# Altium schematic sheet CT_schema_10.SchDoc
size 385 x 278 mm
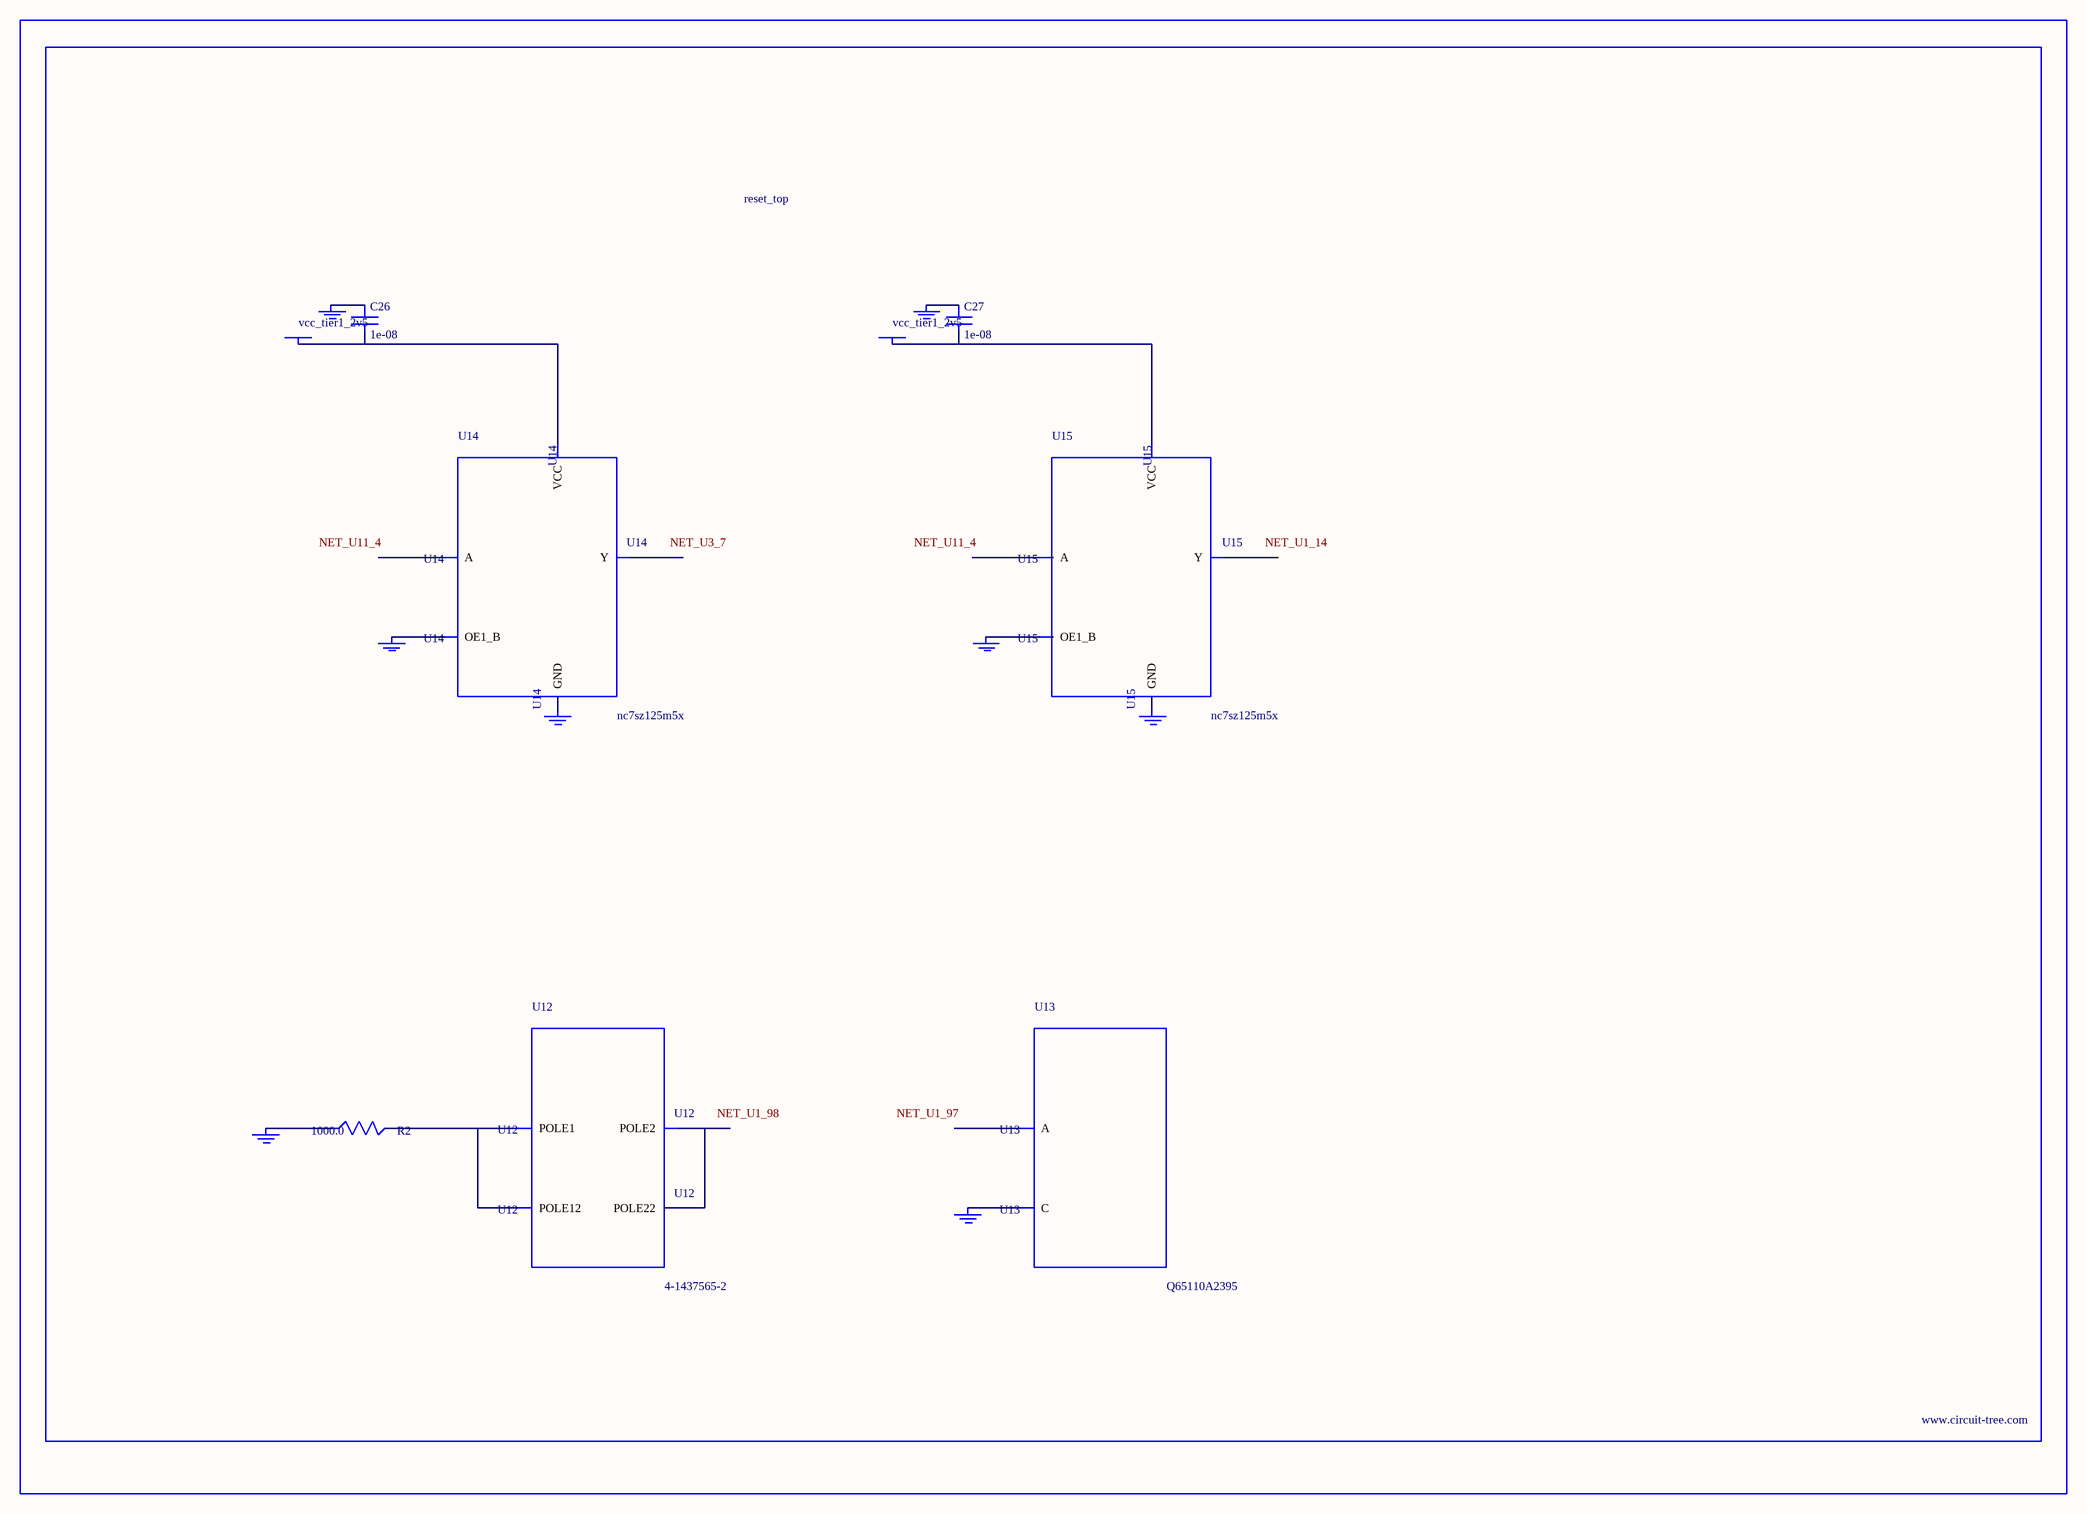
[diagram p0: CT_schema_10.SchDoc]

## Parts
BORDER9  (no value)
C26  1e-08  [C0402]
C27  1e-08  [C0402]
GND_INSTANCE_9_0  (no value)
GND_INSTANCE_9_1  (no value)
GND_INSTANCE_9_2  (no value)
GND_INSTANCE_9_3  (no value)
GND_INSTANCE_9_4  (no value)
GND_INSTANCE_9_5  (no value)
GND_INSTANCE_9_6  (no value)
GND_INSTANCE_9_7  (no value)
POWER_INSTANCE_9_0  vcc_tier1_2v5
POWER_INSTANCE_9_1  vcc_tier1_2v5
R2  1000.0  [R0603]
U12  4-1437565-2  [SW_4-1437565-2]
U13  Q65110A2395  [LGM67K-G1J2-24-Z]
U14  nc7sz125m5x  [NC7SZ125M5X]
U15  nc7sz125m5x  [NC7SZ125M5X]

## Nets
NetC26_1: C26.1 GND_INSTANCE_9_2.0(GND)
NetC26_2: C26.2 POWER_INSTANCE_9_0.0(PWR) U14.5(VCC)
NetC27_1: C27.1 GND_INSTANCE_9_5.0(GND)
NetC27_2: C27.2 POWER_INSTANCE_9_1.0(PWR) U15.5(VCC)
NetGND_INSTANCE_9_0_0: GND_INSTANCE_9_0.0(GND) R2.1
NetGND_INSTANCE_9_1_0: GND_INSTANCE_9_1.0(GND) U13.C
NetGND_INSTANCE_9_3_0: GND_INSTANCE_9_3.0(GND) U14.1(OE1_B)
NetGND_INSTANCE_9_4_0: GND_INSTANCE_9_4.0(GND) U14.3(GND)
NetGND_INSTANCE_9_6_0: GND_INSTANCE_9_6.0(GND) U15.1(OE1_B)
NetGND_INSTANCE_9_7_0: GND_INSTANCE_9_7.0(GND) U15.3(GND)
NetR2_2: R2.2 U12.1(POLE1) U12.2(POLE12)
NetU12_3: U12.3(POLE2) U12.4(POLE22)

Not connected (* = marked no-connect by the designer): U13 A; U14 2(A) 4(Y); U15 2(A) 4(Y)

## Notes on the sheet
- Labels drawn without touching a wire or pin: NET_U1_14, NET_U1_97, NET_U1_98, NET_U3_7, NET_U11_4

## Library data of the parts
BORDER9 = BORDER_PAGE9
C26 C27 = C0402C103K3RAC
GND_INSTANCE_9_0-GND_INSTANCE_9_7 = GND
POWER_INSTANCE_9_0 POWER_INSTANCE_9_1 = PWR
R2 = RC0603JR-071KL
